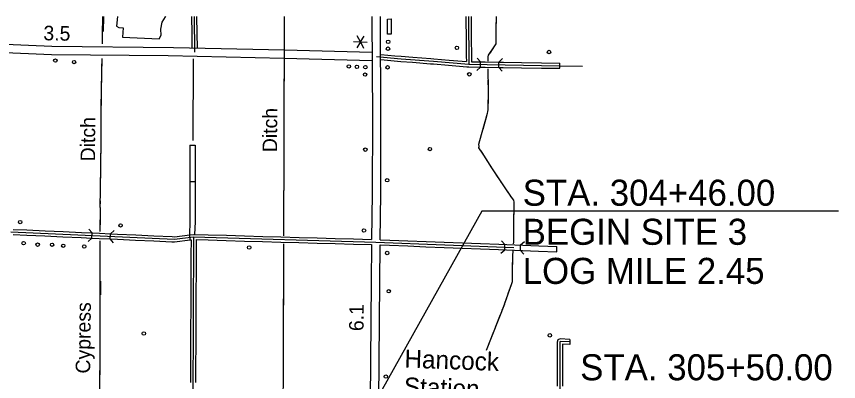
# Model space of a CAD drawing. Extents: x -4306 to 3843, y 131 to 8053.
# Drawn here: x -251 to 3572, y 6356 to 8053 of the extents above; entities that cross this region are included whole.
import ezdxf

# ---------------------------------------------------------------- set-up
doc = ezdxf.new("R2010")
doc.units = 0
for name, color, linetype in [('10', 7, 'Continuous'), ('21', 7, 'Continuous'), ('24', 7, 'Continuous'), ('32', 7, 'Continuous'), ('35', 7, 'Continuous'), ('38', 7, 'Continuous'), ('43', 7, 'Continuous'), ('45', 7, 'Continuous'), ('48', 7, 'Continuous'), ('5', 7, 'Continuous'), ('56', 7, 'Continuous'), ('R_No Plot', 7, 'Continuous')]:
    doc.layers.add(name, color=color, linetype=linetype)

msp = doc.modelspace()

# ---------------------------------------------------------------- linework, layer by layer
at = {"layer": '10'}
for p, q in [((1402.2, 8053), (1404.4, 7580.5)), ((1444.5, 7580.5), (1442.2, 8053)), ((-455.6, 7929.7), (-87, 7915.2)), ((-87, 7915.2), (479.6, 7909.2)), ((-88, 7875.2), (-457.2, 7889.8)), ((1403, 7887.1), (1403.2, 7847)), ((454.6, 7869.8), (-88, 7875.2)), ((1404.4, 7580.5), (1403.2, 7229.5)), ((1443.2, 7229.2), (1444.5, 7580.5)), ((1403.2, 7229.5), (1400.8, 7016.8)), ((1440.8, 7015.4), (1443.2, 7229.2)), ((1400.6, 6992.8), (1398.6, 6820.3)), ((1438.6, 6819.9), (1440.6, 6991.4)), ((1398.6, 6820.3), (1393.1, 6160.5)), ((1433.1, 6159.1), (1438.6, 6819.9))]:
    msp.add_line(p, q, dxfattribs=at)
for points in [[(479.6, 7909.2), (995.2, 7898.2), (1403, 7887.1)], [(1403.2, 7847), (994.2, 7858.2), (454.6, 7869.8)]]:
    msp.add_lwpolyline(points, dxfattribs=at)
at = {"layer": '21'}
msp.add_lwpolyline([(218.4, 8053), (214.3, 8008.3), (224.8, 8001), (245.1, 8000), (242.9, 7956.8), (413.3, 7948.5), (422.3, 7965.6), (420.9, 7994.2), (426.6, 8026.4), (442.7, 8051.4), (443.6, 8053)], dxfattribs=at)
at = {"layer": '32'}
for p, q in [((563.1, 8053), (564.2, 7973.2)), ((575.1, 8053), (577.3, 7887.1)), ((587.1, 8053), (588.2, 7973.6)), ((1839.1, 8053), (1839.3, 8036.8)), ((1839.3, 8036.8), (1840.2, 7952.3)), ((1851.1, 8053), (1853.6, 7830.8)), ((1863.1, 8053), (1863.3, 8037)), ((1863.3, 8037), (1864.2, 7952.6)), ((564.2, 7973.2), (565, 7907.4)), ((588.2, 7973.6), (589, 7906.9)), ((1840.2, 7952.3), (1841.2, 7867.8)), ((1864.2, 7952.6), (1865.2, 7868.1)), ((1443, 7876.8), (1508.6, 7870.7)), ((1423.4, 7866.5), (1537.6, 7856)), ((1443.2, 7852.6), (1506.5, 7846.8)), ((1506.5, 7846.8), (1536.6, 7844.1)), ((1508.6, 7870.7), (1538.6, 7868)), ((1536.6, 7844.1), (1590.8, 7839.9)), ((1537.6, 7856), (1689.2, 7844.5)), ((1538.6, 7868), (1592.7, 7863.9)), ((1590.8, 7839.9), (1675.1, 7833.5)), ((1592.7, 7863.9), (1676.9, 7857.4)), ((1676.9, 7857.4), (1690.2, 7856.4)), ((1689.2, 7844.5), (1853.6, 7830.8)), ((1690.2, 7856.4), (1761.2, 7850.5)), ((1761.2, 7850.5), (1841.4, 7843.8)), ((1841.2, 7867.8), (1841.4, 7843.8)), ((1865.2, 7868.1), (1865.4, 7842.6)), ((1865.4, 7842.6), (1907.7, 7841.9)), ((1907.3, 7817.9), (1907.7, 7841.9)), ((1907.7, 7841.9), (1929, 7841.5)), ((1929, 7841.5), (1992.2, 7840.5)), ((1991.8, 7816.5), (1992.2, 7840.5)), ((1992.2, 7840.5), (2013.5, 7840.1)), ((2013.5, 7840.1), (2098, 7838.7)), ((2098, 7838.7), (2191.6, 7837.4)), ((1675.1, 7833.5), (1688.3, 7832.5)), ((1688.3, 7832.5), (1759.2, 7826.6)), ((1759.2, 7826.6), (1843.4, 7819.6)), ((1843.4, 7819.6), (1853, 7818.8)), ((1853, 7818.8), (1907.3, 7817.9)), ((1853.6, 7830.8), (2275.9, 7823.8)), ((1907.3, 7817.9), (1928.6, 7817.5)), ((1928.6, 7817.5), (1991.8, 7816.5)), ((1991.8, 7816.5), (2013.1, 7816.1)), ((2013.1, 7816.1), (2097.6, 7814.7)), ((2097.6, 7814.7), (2191.2, 7813.4)), ((2191.2, 7813.4), (2275.7, 7812)), ((2191.6, 7837.4), (2276.1, 7836)), ((2275.7, 7812), (2276.1, 7836)), ((2275.7, 7812), (2275.7, 7812)), ((2276.1, 7836), (2276.1, 7836)), ((2276.4, 7823.8), (2381.1, 7822)), ((-277.8, 7052), (484, 7017.2)), ((-265.9, 7039.5), (-203.4, 7036.6)), ((-265.8, 7063.5), (-202.3, 7060.6)), ((-203.4, 7036.6), (-119, 7032.7)), ((-202.3, 7060.6), (-117.9, 7056.7)), ((-117.9, 7056.7), (-33.5, 7052.9)), ((-33.5, 7052.9), (50.9, 7049)), ((50.9, 7049), (101.5, 7046.7)), ((100.4, 7022.7), (101.5, 7046.7)), ((101.5, 7046.7), (135.3, 7045.2)), ((135.3, 7045.2), (185.9, 7042.8)), ((184.9, 7018.9), (186, 7042.8)), ((186, 7042.8), (219.7, 7041.3)), ((219.7, 7041.3), (304.1, 7037.4)), ((304.1, 7037.4), (388.5, 7033.6)), ((483.5, 7029.2), (554.8, 7037.9)), ((554.8, 7037.9), (572.6, 7040.1)), ((557.7, 7014.1), (554.8, 7037.9)), ((572.6, 7040.1), (641, 7038.2)), ((641, 7038.2), (725.4, 7035.8)), ((725.4, 7035.8), (809.9, 7033.4)), ((-119, 7032.7), (-34.6, 7028.9)), ((-34.6, 7028.9), (49.8, 7025)), ((49.8, 7025), (100.4, 7022.7)), ((100.4, 7022.7), (134.2, 7021.2)), ((134.2, 7021.2), (184.9, 7018.9)), ((184.9, 7018.9), (218.6, 7017.3)), ((218.6, 7017.3), (303, 7013.5)), ((303, 7013.5), (387.4, 7009.6)), ((387.4, 7009.6), (471.8, 7005.8)), ((388.5, 7033.6), (472.9, 7029.7)), ((471.8, 7005.8), (484.4, 7005.2)), ((472.9, 7029.7), (483.5, 7029.2)), ((484, 7017.2), (573.1, 7028.1)), ((484.4, 7005.2), (557.7, 7014.1)), ((557.7, 7014.1), (561.1, 7014.5)), ((561.1, 7014.5), (560.7, 6943.7)), ((573.1, 7028.1), (569.1, 6177.8)), ((573.1, 7028.1), (1420.9, 7004.2)), ((585.1, 7015.7), (584.7, 6943.5)), ((585.1, 7015.7), (640.3, 7014.2)), ((640.3, 7014.2), (724.7, 7011.8)), ((724.7, 7011.8), (809.2, 7009.4)), ((809.2, 7009.4), (893.6, 7007.1)), ((809.9, 7033.4), (894.3, 7031)), ((893.6, 7007.1), (978.1, 7004.7)), ((894.3, 7031), (978.8, 7028.7)), ((978.1, 7004.7), (1062.6, 7002.3)), ((978.8, 7028.7), (1063.2, 7026.3)), ((1062.6, 7002.3), (1147, 6999.9)), ((1063.2, 7026.3), (1147.7, 7023.9)), ((1147, 6999.9), (1231.5, 6997.5)), ((1147.7, 7023.9), (1232.1, 7021.5)), ((1231.5, 6997.5), (1315.9, 6995.2)), ((1232.1, 7021.5), (1316.6, 7019.1)), ((1316.6, 7019.1), (1400.8, 7016.8)), ((1420.9, 7004.2), (2062.4, 6979.2)), ((1440.8, 7015.4), (1485.6, 7013.7)), ((1485.6, 7013.7), (1570, 7010.4)), ((1570, 7010.4), (1654.5, 7007.1)), ((1654.5, 7007.1), (1738.9, 7003.8)), ((1738.9, 7003.8), (1823.3, 7000.5)), ((1823.3, 7000.5), (1907.7, 6997.3)), ((1907.7, 6997.3), (1992.2, 6994)), ((1315.9, 6995.2), (1400.6, 6992.8)), ((1440.6, 6991.4), (1484.7, 6989.7)), ((1484.7, 6989.7), (1569.1, 6986.4)), ((1569.1, 6986.4), (1653.5, 6983.1)), ((1653.5, 6983.1), (1738, 6979.8)), ((1738, 6979.8), (1822.4, 6976.6)), ((1822.4, 6976.6), (1906.8, 6973.3)), ((1906.8, 6973.3), (1991.2, 6970)), ((1991.2, 6970), (2177.3, 6962.7)), ((1992.2, 6994), (2178.2, 6986.7)), ((2019.8, 6968.9), (2020.8, 6992.9)), ((2092.9, 6966), (2093.8, 6990)), ((2177.3, 6962.7), (2261.7, 6959.4)), ((2178.2, 6986.7), (2262.7, 6983.4)), ((2261.7, 6959.4), (2262.7, 6983.4)), ((560.7, 6943.7), (560.3, 6859.2)), ((584.7, 6943.5), (584.3, 6859.1)), ((560.3, 6859.2), (559.9, 6774.7)), ((584.3, 6859.1), (583.9, 6774.6)), ((559.9, 6774.7), (559.5, 6690.2)), ((583.9, 6774.6), (583.5, 6690.1)), ((559.5, 6690.2), (559.1, 6605.7)), ((583.5, 6690.1), (583.1, 6605.6)), ((559.1, 6605.7), (558.7, 6521.2)), ((583.1, 6605.6), (582.7, 6521.1)), ((2266.4, 6550.2), (2263.8, 6539.8)), ((2263.8, 6539.8), (2264.5, 6529.6)), ((2278, 6554.9), (2266.4, 6550.2)), ((2276.5, 6541.3), (2275.9, 6538.7)), ((2276.5, 6541.3), (2275.9, 6538.7)), ((2275.9, 6538.7), (2276.5, 6530)), ((2275.9, 6538.7), (2276.5, 6530)), ((2280, 6542.7), (2276.5, 6541.3)), ((2280, 6542.7), (2276.5, 6541.3)), ((2323.3, 6552.4), (2278, 6554.9)), ((2322.7, 6540.4), (2280, 6542.7)), ((2322.7, 6540.4), (2280, 6542.7)), ((2323.3, 6552.4), (2322, 6528.4)), ((558.7, 6521.2), (558.3, 6436.7)), ((582.7, 6521.1), (582.3, 6436.6)), ((2264.5, 6503.4), (2264.4, 6418.9)), ((2264.5, 6529.6), (2264.5, 6503.4)), ((2276.5, 6530), (2276.2, 6245.5)), ((2276.5, 6530), (2276.2, 6245.5)), ((2288.5, 6503.4), (2288.4, 6418.9)), ((2322, 6528.4), (2288.5, 6530.2)), ((2288.5, 6530.2), (2288.5, 6503.4)), ((558.3, 6436.7), (557.9, 6352.2)), ((582.3, 6436.6), (581.9, 6352.1)), ((2264.4, 6418.9), (2264.3, 6334.5)), ((2288.4, 6418.9), (2288.3, 6334.4))]:
    msp.add_line(p, q, dxfattribs=at)
at = {"layer": '35'}
msp.add_line((154.2, 8053), (152.5, 7982.5), dxfattribs=at)
at = {"layer": '38'}
for p, q in [((2020.3, 6980.9), (2020.3, 6980.9)), ((2093.3, 6978), (2093.3, 6978))]:
    msp.add_line(p, q, dxfattribs=at)
for points in [[(1891, 7859.1), (1907.7, 7841.9)], [(1992.2, 7840.5), (2009.5, 7857.2)], [(1907.3, 7817.9), (1890.1, 7801.2)], [(2008.5, 7799.2), (1991.8, 7816.5)], [(85.3, 7064.4), (101.5, 7046.7)], [(185.9, 7042.8), (203.6, 7059)], [(100.4, 7022.7), (82.7, 7006.5)], [(201, 7001.1), (184.8, 7018.9)], [(2020.8, 6992.9), (2004.5, 7010.5)], [(2111.4, 7006.3), (2093.8, 6990)], [(2002.2, 6952.6), (2019.8, 6968.9)], [(2092.9, 6966), (2109.2, 6948.4)]]:
    msp.add_lwpolyline(points, dxfattribs=at)
at = {"layer": '43'}
for points in [[(148.8, 7925.6), (150.4, 8047.3), (150.5, 8053)], [(149.5, 7978.4), (150.4, 8041.8)], [(994, 8053), (994.3, 8011.8), (994.3, 7898.3), (994, 7850.2), (992.7, 7679.5), (992.1, 7501.2), (993, 7416.6), (992.4, 7289.5), (991, 7200.5)], [(994.1, 8035.8), (994.3, 8011.8), (994.3, 7972.4)], [(1979.9, 8053), (1979.9, 8049), (1978.7, 7989.5)], [(1979.9, 8053), (1979.9, 8049), (1978.9, 8000.9)], [(148.8, 7925.6), (149.3, 7957.3)], [(1978.7, 7989.5), (1979.2, 7933.6), (1978.8, 7925.1), (1973.1, 7916.2), (1943.4, 7872.3), (1941.1, 7865.8), (1940.9, 7844.8)], [(1978.7, 7989.5), (1979, 7957.8)], [(994.3, 7951.3), (994.3, 7898.3), (994.2, 7887.9)], [(1979.2, 7936.7), (1979.2, 7933.6), (1978.8, 7925.1), (1973.1, 7916.2), (1950, 7882.1)], [(138.8, 7164.7), (140.3, 7249.7), (143, 7470.6), (143.8, 7631), (146.4, 7783.1), (147.7, 7857.9)], [(146.9, 7808.9), (147.7, 7857.9)], [(994.1, 7866.8), (994, 7850.2), (993.6, 7803.4)], [(1941.1, 7863.4), (1940.9, 7844.8)], [(1940.8, 7809.8), (1943, 7711.5), (1942.1, 7620.9), (1938.7, 7602.4), (1910.7, 7502.8), (1898.1, 7457.6), (1899.2, 7450.2), (1898.4, 7442.8), (1921.3, 7408.2), (1957.9, 7349.8), (2011.5, 7269.8), (2049.2, 7213.8), (2060.3, 7198.5), (2061.8, 7190.1), (2061.9, 7172.8), (2060.3, 7088.7), (2060.1, 7004.5), (2059.8, 6996)], [(1940.8, 7809.8), (1941.5, 7778.1)], [(145.4, 7724.4), (146.4, 7783.1), (146.5, 7787.8)], [(993.5, 7782.3), (993, 7719)], [(1942, 7757), (1943, 7711.5), (1942.8, 7693.6)], [(144.5, 7671.6), (145, 7703.3)], [(992.8, 7697.8), (992.7, 7679.5), (992.7, 7666.2)], [(143.9, 7639.9), (144.5, 7671.6)], [(992.7, 7666.2), (992.5, 7634.5)], [(1942.6, 7672.5), (1942.1, 7620.9), (1940, 7609.3)], [(143.4, 7555.5), (143.7, 7618.8)], [(992.5, 7613.4), (992.3, 7550)], [(1934.9, 7588.9), (1917.7, 7527.9)], [(143, 7471), (143.3, 7534.3)], [(992.2, 7528.9), (992.1, 7501.2), (992.5, 7465.5)], [(1912, 7507.5), (1910.7, 7502.8), (1898.1, 7457.6), (1899.2, 7450.2), (1898.8, 7446.2)], [(142, 7386.5), (142.7, 7449.8)], [(992.7, 7444.4), (993, 7416.6), (992.8, 7381)], [(1908.2, 7428), (1921.3, 7408.2), (1942.3, 7374.6)], [(141, 7302), (141.7, 7365.4)], [(992.7, 7359.9), (992.4, 7296.5)], [(1953.5, 7356.7), (1957.9, 7349.8), (1971, 7330.3)], [(1971, 7330.3), (1988.6, 7304)], [(139.8, 7217.5), (140.3, 7249.7), (140.7, 7280.9)], [(992.2, 7275.4), (991.2, 7212)], [(2000.4, 7286.4), (2011.5, 7269.8), (2035.7, 7233.8)], [(138.8, 7164.7), (139.4, 7196.4)], [(991, 7200.5), (991.6, 7124.9), (991.2, 7032.7)], [(991, 7200.5), (991.3, 7168.8)], [(2047.5, 7216.3), (2049.2, 7213.8), (2060.3, 7198.5), (2061.8, 7190.1), (2061.9, 7172.8), (2061.6, 7157.2)], [(138.8, 7164.7), (137.5, 7053.9)], [(138.8, 7164.7), (138.5, 7133)], [(138.2, 7111.9), (137.5, 7053.9)], [(991.4, 7147.7), (991.6, 7124.9), (991.4, 7084.3)], [(2061.2, 7136), (2060.3, 7088.7), (2060.3, 7072.7)], [(991.3, 7063.2), (991.2, 7032.7)], [(2060.2, 7051.6), (2060.1, 7004.5), (2059.8, 6996)], [(137, 7010.5), (136.7, 6978.4), (137.2, 6875.4), (136.8, 6800.3), (136.9, 6727.5), (136.9, 6612.5), (136.7, 6457.1), (136.1, 6359.3), (136, 6263.3), (137.2, 6210)], [(137, 7010.5), (136.7, 6978.8)], [(990.8, 6996.5), (990.7, 6986.2), (991, 6793.8), (990.1, 6688.9), (989.1, 6602.1), (990.1, 6491.2), (989.9, 6377.6), (988.5, 6273.2), (989.3, 6201.9), (988.9, 6184.6)], [(990.8, 6996.5), (990.7, 6986.2), (990.8, 6964.8)], [(2018.5, 6715.3), (2052.2, 6811.3), (2055.6, 6821.5), (2055.7, 6833.3), (2055.3, 6856.5), (2057.5, 6941.1), (2058.4, 6963.3)], [(2057.2, 6930.7), (2057.5, 6941.1), (2058.4, 6963.3)], [(136.8, 6957.7), (137.1, 6894.3)], [(990.8, 6943.7), (990.9, 6880.3)], [(2055.5, 6846.3), (2055.3, 6856.5), (2056.7, 6909.6)], [(137.2, 6873.2), (136.8, 6809.8)], [(990.9, 6859.2), (991, 6795.8)], [(140.7, 6822.4), (140.3, 6759)], [(2036, 6765.1), (2052.2, 6811.3), (2055.6, 6821.5), (2055.6, 6825.2)], [(136.8, 6788.7), (136.9, 6727.5), (136.9, 6725.3)], [(990.8, 6774.7), (990.3, 6711.4)], [(2018.5, 6715.3), (2029, 6745.2)], [(136.9, 6704.2), (136.9, 6640.8)], [(2018.5, 6715.3), (1934.1, 6500.6)], [(2018.5, 6715.3), (2006.9, 6685.8)], [(990.1, 6690.2), (990.1, 6688.9), (989.4, 6626.9)], [(1999.2, 6666.1), (1976, 6607.2)], [(136.9, 6619.7), (136.9, 6612.5), (136.8, 6556.3)], [(989.1, 6605.7), (989.1, 6602.1), (989.6, 6542.4)], [(1968.3, 6587.5), (1945.1, 6528.5)], [(136.8, 6535.2), (136.7, 6503.5)], [(136.7, 6503.5), (136.7, 6471.8)], [(989.8, 6521.3), (990.1, 6491.2), (990.1, 6489.6)], [(990.1, 6489.6), (990, 6457.9)], [(136.6, 6450.7), (136.2, 6387.4)], [(990, 6436.8), (989.9, 6377.6), (989.8, 6373.4)], [(136.1, 6366.2), (136.1, 6359.3), (136, 6302.9)]]:
    msp.add_lwpolyline(points, dxfattribs=at)
at = {"layer": '45'}
for p, q in [((556, 7455.4), (555.7, 7370.9)), ((556, 7455.4), (580, 7455.3)), ((580, 7455.3), (579.7, 7370.8)), ((555.7, 7370.9), (555.7, 7357.6)), ((555.7, 7357.6), (555.9, 7295.9)), ((579.7, 7370.8), (579.7, 7357.6)), ((579.7, 7357.6), (579.9, 7296)), ((555.9, 7286.4), (555.8, 7240.9)), ((555.9, 7295.9), (555.9, 7286.4)), ((555.9, 7286.4), (579.9, 7286.3)), ((579.9, 7286.3), (579.8, 7240.9)), ((579.9, 7296), (579.9, 7286.3)), ((555.8, 7240.9), (555.9, 7201.8)), ((579.8, 7240.9), (579.9, 7201.9)), ((555.9, 7201.8), (556, 7178.2)), ((579.9, 7201.9), (580, 7178.1)), ((556, 7178.2), (555.6, 7117.5)), ((580, 7178.1), (579.6, 7117.3)), ((555.6, 7117.5), (555.5, 7099.7)), ((579.6, 7117.3), (579.5, 7099.2)), ((555.5, 7099.7), (553.6, 7037.8)), ((579.5, 7099.2), (577.7, 7040))]:
    msp.add_line(p, q, dxfattribs=at)
at = {"layer": '48'}
for p, q in [((1348.8, 7934.5), (1334.2, 7963)), ((1348.8, 7934.5), (1366.1, 7961.4)), ((1316.8, 7936.1), (1348.8, 7934.5)), ((1348.8, 7934.5), (1331.4, 7907.6)), ((1348.8, 7934.5), (1380.7, 7932.9)), ((1348.8, 7934.5), (1363.4, 7906))]:
    msp.add_line(p, q, dxfattribs=at)
at = {"layer": '5'}
msp.add_line((570.5, 7476.7), (572.4, 7856.4), dxfattribs=at)
at = {"layer": '56'}
msp.add_lwpolyline([(1491.5, 7971.2), (1475.5, 7971.1), (1475.1, 8041.1), (1491.1, 8041.2)], close=True, dxfattribs=at)
for centre in [(1477.9, 7935.1), (1797.6, 7906.9), (1477.1, 7903.1), (2225.6, 7887.6), (-70, 7848), (17.1, 7840.8), (1294.8, 7820.7), (1332.4, 7818.8), (1371.8, 7817.1), (1475.2, 7816.4), (1370.6, 7782.9), (1855.2, 7784.2), (1371.6, 7434), (1672.1, 7436.6), (1473.2, 7291.9), (-233.4, 7097.3), (233.5, 7081.9), (1365.4, 7058.3), (-217.5, 6999.3), (-152.4, 6992.5), (-85.2, 6992.1), (-33.4, 6987.3), (64.3, 6983.8), (831.6, 6979.2), (1473.4, 6953.6), (1480.5, 6775.9), (341.6, 6579.4), (2229.6, 6571), (1467.2, 6379.5)]:
    msp.add_circle(centre, 8, dxfattribs=at)
at = {"layer": 'R_No Plot'}
for p, q in [((1913.7, 7148.4), (887.6, 5313.5)), ((3572.5, 7148.4), (1913.7, 7148.4))]:
    msp.add_line(p, q, dxfattribs=at)

# ---------------------------------------------------------------- texts
at = {"layer": '24'}
for s, p in [('Hancock', (1552.5, 6421.1)), ('Station', (1549.9, 6291.5))]:
    msp.add_text(s, height=84.49, rotation=357.963, dxfattribs=at).set_placement(p)
at = {"layer": '43'}
for s, rotation, p in [('Ditch', 89.818, (961.3, 7422)), ('Ditch', 89.818, (114.8, 7379.3)), ('Cypress', 89.4245, (91.9, 6393.2))]:
    msp.add_text(s, height=67.59, rotation=rotation, dxfattribs=at).set_placement(p)
at = {"layer": '48'}
for s, rotation, p in [('3.5', 358.8534, (-126.2, 7942.5)), ('6.1', 89.5179, (1363.5, 6590.5))]:
    msp.add_text(s, height=67.59, rotation=rotation, dxfattribs=at).set_placement(p)
at = {"layer": 'R_No Plot'}
for s, p in [('STA. 304+46.00', (2103.5, 7173.3)), ('BEGIN SITE 3', (2103.5, 6991.7)), ('LOG MILE 2.45', (2103.5, 6810.1)), ('STA. 305+50.00', (2370.8, 6362.1))]:
    msp.add_text(s, height=121.064, dxfattribs=at).set_placement(p)

doc.saveas('drawing.dxf')
